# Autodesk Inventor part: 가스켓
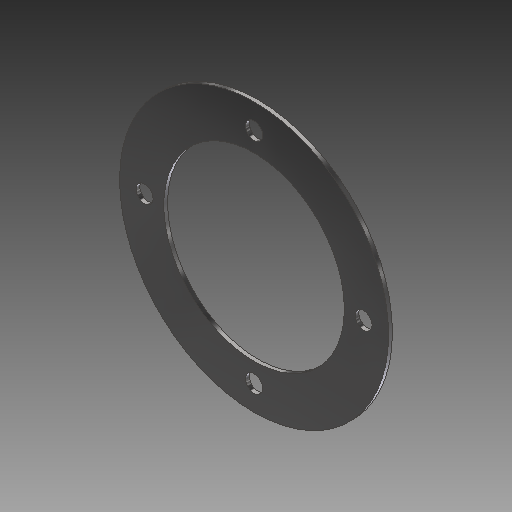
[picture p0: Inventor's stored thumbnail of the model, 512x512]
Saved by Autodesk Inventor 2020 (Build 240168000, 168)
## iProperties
Created: 2024-02
Part Number: 가스켓
Material: 스테인리스강
Document SubType Name: Modeling
Designer: mdu-01
Density: 1 g/cm^3
Appearance: 반광택
Author: mdu-01
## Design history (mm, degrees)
sketch "스케치1"
  geometry: C1 r 35 at (0, 0); C2 r 23.5 at (0, 0); C3 r 2.25 at (0, 28.5); C4 r 2.25 at (28.5, 0); C5 r 2.25 at (-28.5, 0); C6 r 2.25 at (0, -28.5); A1 r 28.5 centre (0, 0) between (0, 28.5) and (28.5, 0); 1 further point
  constraints: 7 centre point, 4 point on circle, 3 coincident, 3 equal radius, 2 horizontal alignment, 2 vertical alignment
  dimensions: "d0" = 70 diameter of C1; "d1" = 47 diameter of C2; "d2" = 57 diameter of A1; "d3" = 4.5 diameter of C3
extrude "돌출1" new body sketch "스케치1" distance "d4" = 1; taper "d5" = 0 deg
node "솔리드1"
